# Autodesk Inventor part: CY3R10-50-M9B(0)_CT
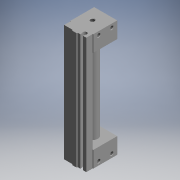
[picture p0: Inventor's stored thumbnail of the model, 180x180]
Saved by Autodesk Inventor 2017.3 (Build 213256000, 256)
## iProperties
Part Number: CY3R10-50-M9B(0)_CT
Material: Generic
Catalog Web Link: www.cadenas.de
Description: CY3R CT-Magnetically Coupled Rodless Cylinder Direct Mount Type
Vendor: SMC
Document SubType Name: Modeling
Designer: partserver
Manufacturer: SMC
Mass: 51.0016 g
Surface Area: 189.205 cm^2
Volume: 51.0016 cm^3
Density: 1 g/cm^3
Appearance: PSOLRGB-192-192-192
Category: PARTsolutions
Company: SMC
Title: CY3R10-50-M9B_CT
Author: Cadenas PARTsolutions
Comments: Magnetically Coupled Rodless Cylinder Direct Mount Type
PSOL_IDENT_0: {$CADENAS_DATA\23d-libs\smc_jp\actuator\rodless_cylinders\cy3\cy3r\parts\cy3r_cylinder_tube.prj},239
PSOL_IDENT_1: {VTYP=3D},{NB=CY3R10-50-M9B(0)_CT},{LINA=CY3R10-50-M9B_CT},{NN=CY3R CT},{DATE=09.12.2020 02:54:07},
PSOL_IDENT_2: {GEOMDATE=26.10.2020 01:54:32},{VERSION=},{LINEID=20},{WBVAR=PIPING,THREAD1,STROKE,RAIL,AUTOSWITCH,N
PSOL_IDENT_3: UMBER,THREAD2,OMSC},{WBNUMERIC=STROKE}  {NB=CY3R10-50-M9B(0)_CT},{LINA=CY3R10-50-M9B_CT},{KT=DUMMY},
PSOL_IDENT_4: {PIPING=},{PIPINGX='','(-) Standard type','G','(G) Centralized piping type'},{BORE=10},{THREAD1=},{T
PSOL_IDENT_5: HREAD1X='','(-) M thread'},{STROKE=50},{STROKEX=[25:500/1]},{RAIL=},{RALLX='', '(-) With switch rail'
PSOL_IDENT_6: , 'N', '(N) Without switch rail'},{AUTOSWITCH=-M9B},{AUTOSWITCHX='','(-) Without autoswitch (Built-i
PSOL_IDENT_7: n magnet)','-A90','A90','-A93','A93','-A96','A96','-M9N','M9N','-M9P','M9P','-M9B','M9B','-M9NW','M9
PSOL_IDENT_8: NW','-M9PW','M9PW','-M9BW','M9BW','-M9NA','M9NA','-M9PA','M9PA','-M9BA','M9BA'},{NUMBER=},{NUMBERX=''
PSOL_IDENT_9: ,'(-) 2 Pcs','S','(S) 1 Pcs'},{THREAD2=0},{OMSC=},{OMSCX= '','(-) None','-XC57','(XC57) With floatin
PSOL_IDENT_10: g joint'},{SMIN1=25},{SMIN2=50},{SMAX1=500},{SMAX2=500},{ORDER=CY3R10-50-M9B},{A=9.0},{B=6.5},{C=3.2
PSOL_IDENT_11: },{CB=2},{CR=0.5},{D=12.0},{G=4.0},{GP=27},{GW=25.5},{H=26},{HA=24},{HB=14.0},{HC=25},{HP=14.0},{HP1=
PSOL_IDENT_12: 14.0},{HP2=0.0},{HR=24},{HS=5.0},{HT=14.0},{HT1=14.0},{HT2=0.0},{JXE=M4x0.7x6},{JRA=4},{JRP=0.70},{E=
PSOL_IDENT_13: 6},{L=38},{LD=3.5},{M=4.0},{MM=M3x0.5},{MRA=3},{MRP=0.50},{N=4.5},{PW=26},{Q=68},{QW=14},{T=17.5},{W
PSOL_IDENT_14: P=13.0},{WS=8},{Y=39.5},{Z=76},{P=M5x0.8},{PRA=5},{PRP=0.8},{PRND=0.000},{PTN=-},{PTF=-},{PGND=0.000
PSOL_IDENT_15: },{PR1=5.000},{PD=6.00},{HH=4.5},{R=2.1},{LH=3},{AA=32.0},{AA1=28.0},{AA2=32.0},{BB=44.0},{BB1=48.0}
PSOL_IDENT_16: ,{BB2=44.0},{PR=2.5},{PH=2.4},{PLV=12.0},{PLH=4.0},{L1=0.0},{L2=0.5}
NB: CY3R10-50-M9B(0)_CT
NN: CY3R CT
NT: Magnetically Coupled Rodless Cylinder Direct Mount Type
NBSYN: $ORDER.($THREAD2.)_CT
LINA: CY3R10-50-M9B_CT
CATALOG: SMC (JP
PIPING: (-) Standard type
BORE: 10
THREAD1: (-) M thread
STROKE: 50
RAIL: (-) With switch rail
AUTOSWITCH: M9B Solid state-General-Grommet-Indicator light:Yes-2 wire-In line
NUMBER: (-) 2 Pcs
THREAD2: on
OMSC: (-) None
SMIN1: 25
SMIN2: 50
SMAX1: 500
SMAX2: 500
A: 9
B: 6.5
C: 3.2
CB: 2
CR: 0.5
D: 12
G: 4
GP: 27
GW: 25.5
H: 26
HA: 24
HB: 14
HC: 25
HP: 14
HR: 24
HS: 5
HT: 14
JXE: M4x0.7x6
E: 6
L: 38
LD: 3.5
M: 4
MM: M3x0.5
N: 4.5
PW: 26
Q: 68
QW: 14
T: 17.5
WP: 13
WS: 8
Y: 39.5
Z: 76
P: M5x0.8
PTF: -
HH: 4.5
R: 2.1
LH: 3
AA1: 28
AA2: 32
BB1: 48
BB2: 44
PR: 2.5
PH: 2.4
PLV: 12
PLH: 4
L1: 0
L2: 0.5
SUPPLIER: SMC
ARTICLENO: CY3R10-50-M9B(0)_CT
BOMINFO: CY3R10-50-M9B_CT
CREATOR: CADENAS GmbH
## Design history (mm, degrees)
sketch "Sketch_1"
  geometry: L1 (0, -91)-(0, 0); L2 (0, 0)-(6, 0); L3 (6, 0)-(6, -91); L4 (6, -91)-(0, -91); L5 (0, -91)-(0, 0)
  constraints: 10 end point
revolve "Revolution1" sketch "Sketch_1" stored, may be unused: angle "d0" = 360 deg
sketch "Sketch_2"
  geometry: L1 (-14, -13)-(11, -13); L2 (11, -13)-(11, 13); L3 (11, 13)-(-14, 13); L4 (-14, 13)-(-14, -13)
  constraints: 8 end point
extrude "Extrusion1" join sketch "Sketch_2" distance "d1" = 17.5; taper "d2" = 0 deg
sketch "Sketch_3"
  geometry: L1 (-14, -13)-(11, -13); L2 (11, -13)-(11, 13); L3 (11, 13)-(-14, 13); L4 (-14, 13)-(-14, -13)
  constraints: 8 end point
extrude "Extrusion2" join sketch "Sketch_3" distance "d3" = 17.5; taper "d4" = 0 deg
sketch "Sketch_50"
  geometry: L1 (-13.5, -20)-(-10, -20); L2 (-10, -20)-(-10, -17.97); L3 (-7, -17.97)-(-7, -20); L4 (-7, -20)-(-4.5, -20); L5 (-4.5, -20)-(-3.5, -21); L6 (-3.5, -21)-(0.5, -21); L7 (0.5, -21)-(1.5, -20); L8 (1.5, -20)-(10.5, -20); L9 (10.5, -20)-(10.5, -13); L10 (10.5, -13)-(-13.5, -13); L11 (-13.5, -13)-(-13.5, -20); A1 r 2.1 centre (-8.5, -16.5) between (-7, -17.97) and (-10, -17.97)
  constraints: 22 end point, 2 point on circle, 1 centre point
extrude "Extrusion3" join sketch "Sketch_50" distance "d5" = 126; taper "d6" = 0 deg
sketch "Sketch_7"
  geometry: L1 (11, 7)-(-14, 7); L2 (-14, 7)-(-14, 9); L3 (-14, 9)-(-13.621, 8.621); L4 (-13.621, 8.621)-(-8, 8.621); L5 (-8, 8.621)-(-8, 8.75); L6 (-8, 8.75)-(7.8, 8.75); L7 (7.8, 8.75)-(7.8, 10.25); L8 (7.8, 10.25)-(11, 10.25); L9 (11, 10.25)-(11, 7); L10 (11, 7)-(-14, 7)
  constraints: 20 end point
revolve "Revolution2" sketch "Sketch_7" stored, may be unused: angle "d7" = 360 deg
thread "Thread1" dims "d8" = 5.621, "d9" = 0
pattern_linear "Rectangular Pattern1" dims "d12" = 118, "d15" = 14
sketch "Sketch_9"
  geometry: L1 (-10.307, 0)-(-17.5, 0); L2 (-17.5, 0)-(-17.5, 2.5); L3 (-17.5, 2.5)-(-17.067, 2.067); L4 (-17.067, 2.067)-(-11.5, 2.067); L5 (-11.5, 2.067)-(-10.307, 0); L6 (-10.307, 0)-(-17.5, 0)
  constraints: 12 end point
revolve "Revolution3" sketch "Sketch_9" stored, may be unused: angle "d16" = 360 deg
thread "Thread2" dims "d17" = 5.567, "d18" = 0
sketch "Sketch_10"
  geometry: L1 (108.5, 0)-(101.307, 0); L2 (101.307, 0)-(102.5, 2.067); L3 (102.5, 2.067)-(108.067, 2.067); L4 (108.067, 2.067)-(108.5, 2.5); L5 (108.5, 2.5)-(108.5, 0); L6 (108.5, 0)-(101.307, 0)
  constraints: 12 end point
revolve "Revolution4" sketch "Sketch_10" stored, may be unused: angle "d19" = 360 deg
thread "Thread3" dims "d20" = 5.567, "d21" = 0
sketch "Sketch10"
  geometry: 1 further point
hole "Hole1" sketch "Sketch10" at (14, -8.5) diameter "d22" = 5; stored, may be unused: countersink angle "d26" = 90 deg, drill point angle "d28" = 0 deg; dims "d23" = 6, "d24" = 4, "d25" = 2, "d27" = 3
sketch "Sketch11"
  geometry: 1 further point
hole "Hole2" sketch "Sketch11" at (14, 8.5) diameter "d29" = 5; stored, may be unused: countersink angle "d33" = 90 deg, drill point angle "d35" = 0 deg; dims "d30" = 6, "d31" = 4, "d32" = 2, "d34" = 3
sketch "Sketch_46"
  geometry: L1 (-1.25, -9.222)-(0, -9.943); L2 (0, -9.943)-(1.25, -9.222); L3 (1.25, -9.222)-(1.25, -7.778); L4 (1.25, -7.778)-(0, -7.057); L5 (0, -7.057)-(-1.25, -7.778); L6 (-1.25, -7.778)-(-1.25, -9.222); C1 r 2.25 at (0, -8.5); 1 further point
  constraints: 12 end point, 1 centre point
extrude "Extrusion4" join sketch "Sketch_46" distance "d36" = 3; taper "d37" = 0 deg
sketch "Sketch_48"
  geometry: L1 (-1.25, 98.778)-(0, 98.057); L2 (0, 98.057)-(1.25, 98.778); L3 (1.25, 98.778)-(1.25, 100.222); L4 (1.25, 100.222)-(0, 100.943); L5 (0, 100.943)-(-1.25, 100.222); L6 (-1.25, 100.222)-(-1.25, 98.778); C1 r 2.25 at (0, 99.5); 1 further point
  constraints: 12 end point, 1 centre point
extrude "Extrusion5" join sketch "Sketch_48" distance "d38" = 3; taper "d39" = 0 deg
sketch "Sketch14"
  geometry: 1 further point
hole "Hole3" sketch "Sketch14" at (-1.5, -17) diameter "d40" = 5; stored, may be unused: countersink angle "d44" = 90 deg, drill point angle "d46" = 0 deg; dims "d41" = 6, "d42" = 4, "d43" = 2, "d45" = 3
sketch "Sketch_51"
  geometry: L1 (-2.886, -17)-(-2.193, -18.2); L2 (-2.193, -18.2)-(-0.807, -18.2); L3 (-0.807, -18.2)-(-0.114, -17); L4 (-0.114, -17)-(-0.807, -15.8); L5 (-0.807, -15.8)-(-2.193, -15.8); L6 (-2.193, -15.8)-(-2.886, -17); C1 r 2.25 at (-1.5, -17); 1 further point
  constraints: 12 end point, 1 centre point
extrude "Extrusion6" join sketch "Sketch_51" distance "d47" = 3; taper "d48" = 0 deg
node "9_1_XY"
node "9_1_YZ"
node "9_1_ZX"
node "9_1_X"
node "9_1_Y"
node "9_1_Z"
node "9_1_Center"
node "CT_CB1_XY"
node "CT_CB1_YZ"
node "CT_CB1_ZX"
node "CT_CB1_X"
node "CT_CB1_Y"
node "CT_CB1_Z"
node "CT_CB1_Center"
node "CT_CB2_XY"
node "CT_CB2_YZ"
node "CT_CB2_ZX"
node "CT_CB2_X"
node "CT_CB2_Y"
node "CT_CB2_Z"
node "CT_CB2_Center"
node "CT_SW1_XY"
node "CT_SW1_YZ"
node "CT_SW1_ZX"
node "CT_SW1_X"
node "CT_SW1_Y"
node "CT_SW1_Z"
node "CT_SW1_Center"
node "CT_SW2_XY"
node "CT_SW2_YZ"
node "CT_SW2_ZX"
node "CT_SW2_X"
node "CT_SW2_Y"
node "CT_SW2_Z"
node "CT_SW2_Center"
node "HR_XY"
node "HR_YZ"
node "HR_ZX"
node "HR_X"
node "HR_Y"
node "HR_Z"
node "HR_Center"
node "ct_body_XY"
node "ct_body_YZ"
node "ct_body_ZX"
node "ct_body_X"
node "ct_body_Y"
node "ct_body_Z"
node "ct_body_Center"
node "ct_dummy_XY"
node "ct_dummy_YZ"
node "ct_dummy_ZX"
node "ct_dummy_X"
node "ct_dummy_Y"
node "ct_dummy_Z"
node "ct_dummy_Center"
body "Solid1"
other parameters: "d49" = 0, "d50" = 0, "d51" = 0
